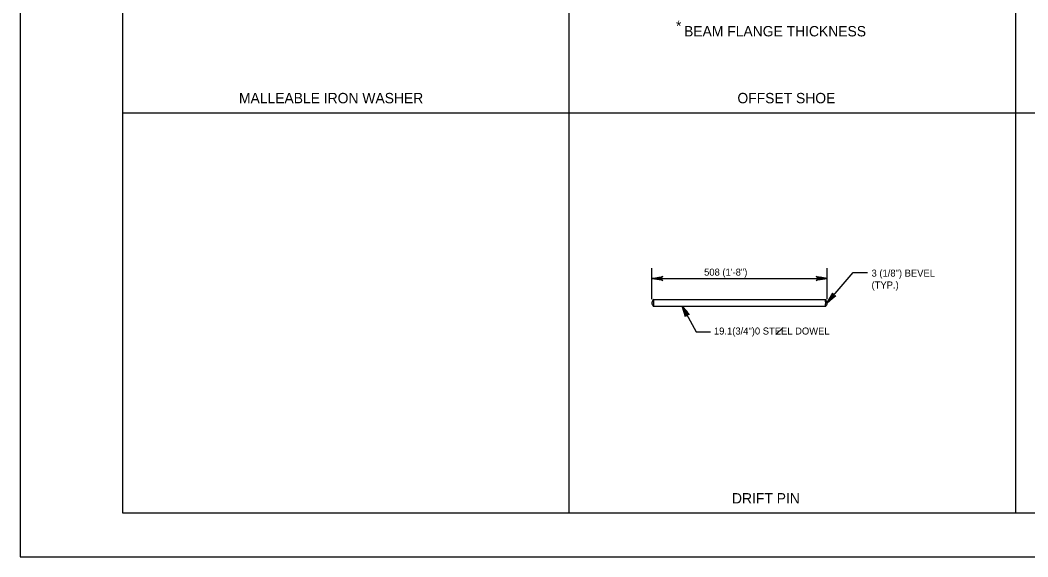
# Model space of a CAD drawing. Extents: x 0 to 36.3, y -66 to 0.
# Drawn here: x 0 to 17.21, y -66 to -56.84 of the extents above; entities that cross this region are included whole.
import ezdxf

# ---------------------------------------------------------------- set-up
doc = ezdxf.new("R2010")
doc.units = 0
for name, color, linetype in [('1', 7, 'Continuous'), ('3', 7, 'Continuous'), ('4', 7, 'Continuous'), ('62', 7, 'Continuous'), ('63', 7, 'Continuous')]:
    doc.layers.add(name, color=color, linetype=linetype)

msp = doc.modelspace()

# ---------------------------------------------------------------- linework, layer by layer
at = {"layer": '1'}
msp.add_lwpolyline([(1.75, -65.25), (33.25, -65.25), (33.25, -44.75), (1.75, -44.75)], close=True, dxfattribs=at)
at = {"layer": '3'}
for p, q in [((9.375, -65.25), (9.375, -44.75)), ((17, -65.25), (17, -44.75)), ((1.75, -58.417), (32.25, -58.417)), ((10.786, -61.602), (10.786, -61.069)), ((13.778, -61.602), (13.778, -61.069)), ((10.904, -61.246), (13.66, -61.246)), ((12.903, -62.206), (13.025, -62.084)), ((11.54, -62.156), (11.785, -62.156))]:
    msp.add_line(p, q, dxfattribs=at)
for points in [[(10.786, -61.246), (10.973, -61.211), (10.958, -61.221), (10.951, -61.233), (10.949, -61.246), (10.951, -61.258), (10.958, -61.271), (10.973, -61.281), (10.786, -61.246), (10.958, -61.271), (10.951, -61.258), (10.786, -61.246), (10.949, -61.246), (10.951, -61.233), (10.786, -61.246), (10.958, -61.221)], [(13.778, -61.246), (13.592, -61.281), (13.606, -61.271), (13.614, -61.258), (13.616, -61.246), (13.614, -61.233), (13.606, -61.221), (13.592, -61.211), (13.778, -61.246), (13.606, -61.221), (13.614, -61.233), (13.778, -61.246), (13.616, -61.246), (13.614, -61.258), (13.778, -61.246), (13.606, -61.271)], [(11.305, -61.722), (11.54, -62.156)], [(11.305, -61.722), (11.425, -61.87), (11.409, -61.862), (11.395, -61.861), (11.383, -61.865), (11.373, -61.873), (11.365, -61.886), (11.363, -61.903), (11.305, -61.722), (11.365, -61.886), (11.373, -61.873), (11.305, -61.722), (11.383, -61.865), (11.395, -61.861), (11.305, -61.722), (11.409, -61.862)]]:
    msp.add_lwpolyline(points, dxfattribs=at)
for points in [[(10.904, -61.226), (10.904, -61.266), (10.786, -61.246)], [(13.66, -61.226), (13.66, -61.266), (13.778, -61.246)], [(11.305, -61.722), (11.335, -61.84), (11.387, -61.812)]]:
    msp.add_lwpolyline(points, close=True, dxfattribs=at)
at = {"layer": '4'}
for p, q in [((10.816, -61.722), (13.749, -61.722)), ((10.817, -61.604), (13.748, -61.604))]:
    msp.add_line(p, q, dxfattribs=at)
for points in [[(13.778, -61.664), (14.225, -61.143), (14.466, -61.143)], [(13.778, -61.664), (13.873, -61.5), (13.871, -61.517), (13.876, -61.531), (13.884, -61.54), (13.895, -61.547), (13.909, -61.549), (13.926, -61.545), (13.778, -61.664), (13.909, -61.549), (13.895, -61.547), (13.778, -61.664), (13.884, -61.54), (13.876, -61.531), (13.778, -61.664), (13.871, -61.517)]]:
    msp.add_lwpolyline(points, dxfattribs=at)
msp.add_lwpolyline([(13.778, -61.664), (13.782, -61.661), (13.781, -61.66)], close=True, dxfattribs=at)
for centre, radius, start, end in [((10.859, -61.664), 0.0728, 125.2575, 233.7233), ((11.116, -61.666), 0.305, 168.3368, 190.6439), ((13.706, -61.664), 0.0728, 306.2767, 54.7425), ((13.449, -61.666), 0.305, 349.3561, 11.6632)]:
    msp.add_arc(centre, radius, start, end, dxfattribs=at)
at = {"layer": '62'}
msp.add_line((0, -66), (0, -66), dxfattribs=at)
at = {"layer": '63'}
msp.add_lwpolyline([(0, -66), (34, -66), (34, -44), (0, -44)], close=True, dxfattribs=at)

# ---------------------------------------------------------------- texts
at = {"layer": '3'}
for s, height, p in [('*', 0.177, (11.198, -57.023)), (' BEAM FLANGE THICKNESS', 0.17717, (11.27, -57.113)), ('MALLEABLE IRON WASHER', 0.17717, (3.736, -58.255)), ('OFFSET SHOE', 0.17717, (12.247, -58.255)), ('508 (1\'-8")', 0.12, (11.678, -61.198)), ('3 (1/8") BEVEL', 0.12, (14.537, -61.215)), ('(TYP.)', 0.12, (14.537, -61.418)), ('19.1(3/4")0 STEEL DOWEL', 0.12, (11.846, -62.204)), ('DRIFT PIN', 0.1772, (12.154, -65.089))]:
    msp.add_text(s, height=height, dxfattribs=at).set_placement(p)

doc.saveas('drawing.dxf')
